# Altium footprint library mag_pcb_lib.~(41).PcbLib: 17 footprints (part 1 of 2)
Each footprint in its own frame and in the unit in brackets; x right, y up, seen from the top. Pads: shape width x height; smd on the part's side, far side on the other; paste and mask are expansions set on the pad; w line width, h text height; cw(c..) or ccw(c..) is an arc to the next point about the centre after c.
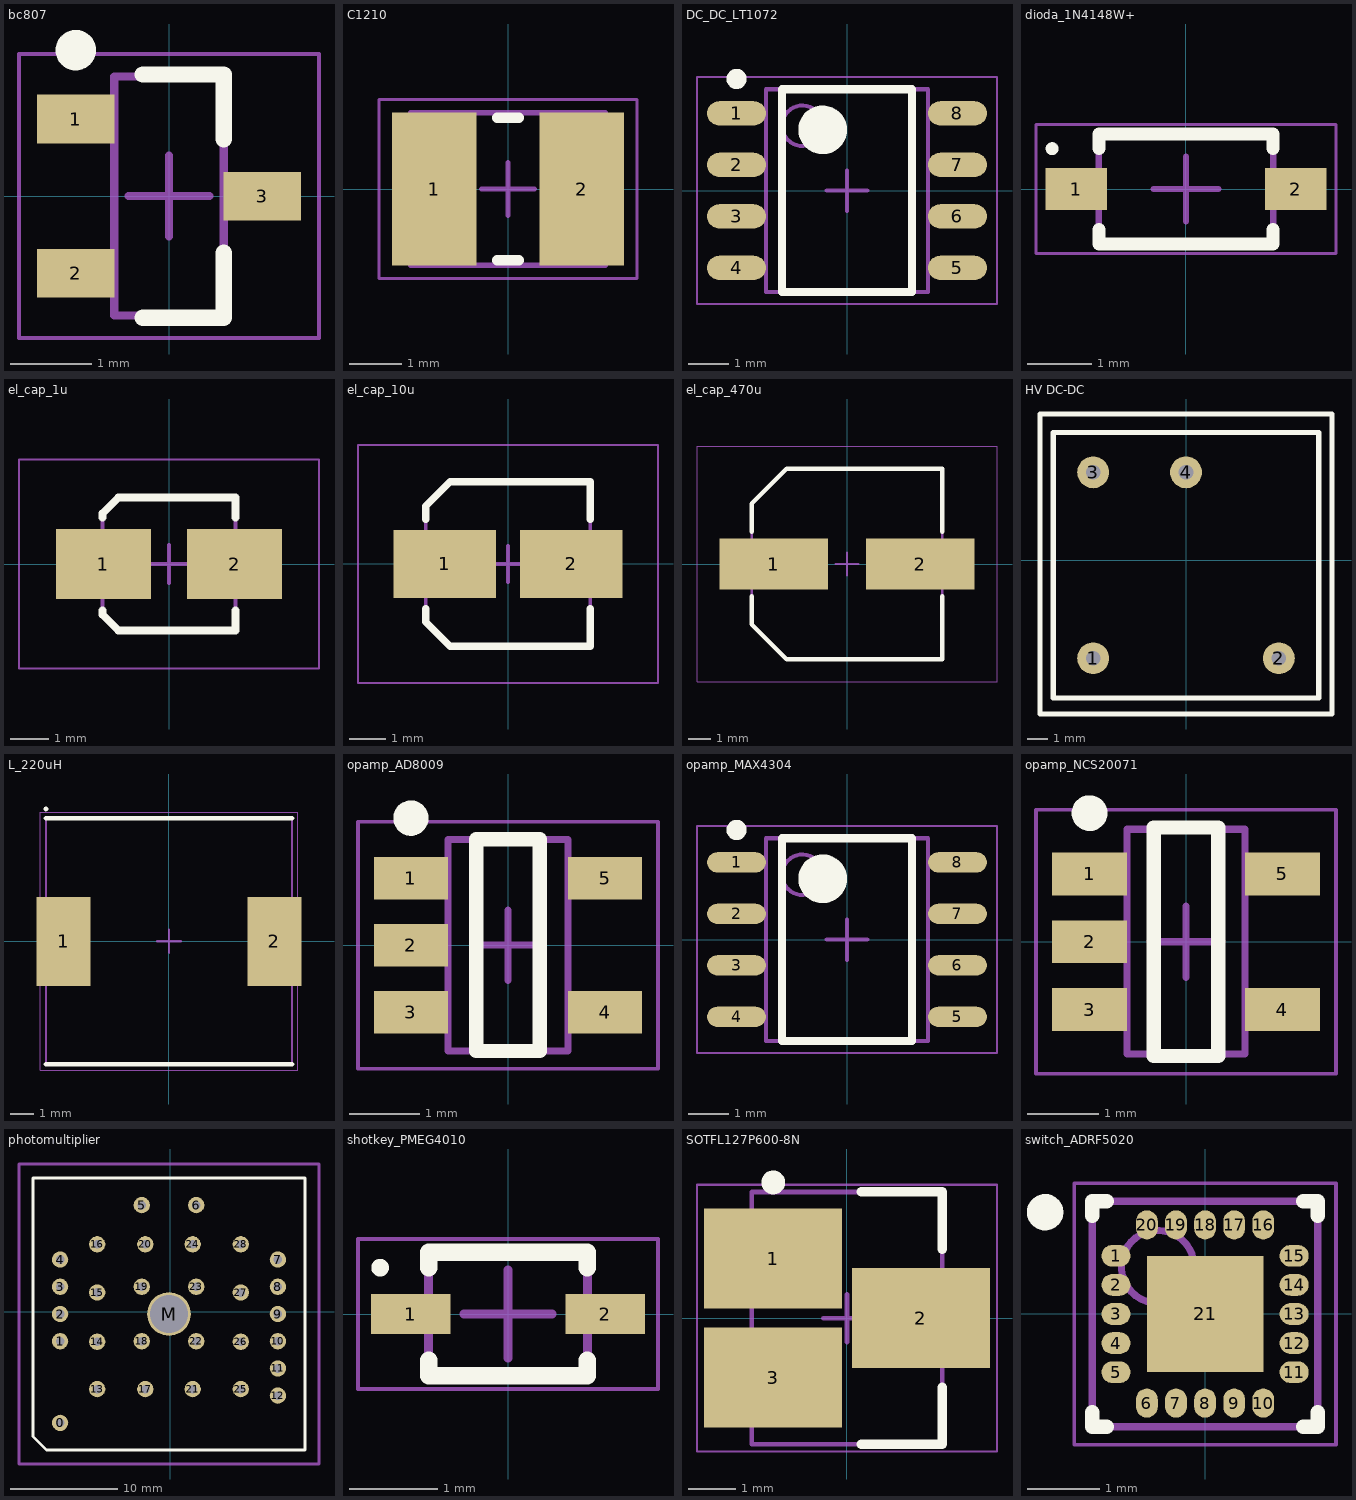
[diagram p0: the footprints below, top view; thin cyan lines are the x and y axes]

## bc807 [mm]
height 1
pads (3):
  rect 0.95x0.6 smd: 1(-1.15,0.95) 2(-1.15,-0.95) 3(1.15,0)
Top Overlay:
  circle w0.25: c-1.15,1.8 r0.125
  lines w0.2: -0.325,-1.5 0.675,-1.5 0.675,-0.7 ; -0.325,1.5 0.675,1.5 0.675,0.7
Mechanical 13:
  lines w0.1: -0.675,-1.475 0.675,-1.475 0.675,1.475 -0.675,1.475 -0.675,-1.475
Mechanical 15:
  lines w0.05: -1.85,-1.75 1.85,-1.75 1.85,1.75 -1.85,1.75 -1.85,-1.75
  lines w0.1: -0.5,0 0.5,0 ; 0,-0.5 0,0.5
3D body: height 1, standoff 0.1, extent -0.675,-1.475 0.675,1.475

## C1210 [mm]
height 1.9
pads (2):
  rect 1.6x2.9 smd: 1(-1.4,0) 2(1.4,0)
Top Overlay:
  lines w0.2: -0.2,-1.35 0.2,-1.35 ; -0.2,1.35 0.2,1.35
Mechanical 13:
  lines w0.1: -1.85,-1.45 1.85,-1.45 1.85,1.45 -1.85,1.45 -1.85,-1.45
Mechanical 15:
  lines w0.05: -2.45,-1.7 2.45,-1.7 2.45,1.7 -2.45,1.7 -2.45,-1.7
  lines w0.1: -0.5,0 0.5,0 ; 0,-0.5 0,0.5
3D body: height 1.9, standoff 0, extent 1.25,-1.45 1.85,1.45
3D body: height 1.9, standoff 0, extent -1.85,-1.45 -1.25,1.45
3D body: height 1.9, standoff 0, extent -1.25,-1.45 1.25,1.45

## DC_DC_LT1072 [mm]
height 1.76
pads (8):
  oval 1.45x0.6 smd: 1(-2.725,1.905) 2(-2.725,0.635) 3(-2.725,-0.635) 4(-2.725,-1.905) 5(2.725,-1.905) 6(2.725,-0.635) 7(2.725,0.635) 8(2.725,1.905)
Top Overlay:
  circle w0.25: c-2.725,2.755 r0.125
  circle w0.6: c-0.6,1.5 r0.3
  lines w0.2: -1.6,-2.5 -1.6,2.5 1.6,2.5 1.6,-2.5 -1.6,-2.5
Mechanical 13:
  circle w0.1: c-1.1,1.6 r0.5
  lines w0.1: -2,-2.5 -2,2.5 2,2.5 2,-2.5 -2,-2.5
Mechanical 15:
  lines w0.05: -3.7,-2.8 -3.7,2.8 3.7,2.8 3.7,-2.8 -3.7,-2.8
  lines w0.1: -0.5,0 0.5,0 ; 0,-0.5 0,0.5
3D body: height 1.76, standoff 0.25, extent -2,-2.5 2,2.5

## dioda_1N4148W+ [mm] "SODFL, 2-Leads, Body 1.60x3.80mm, IPC Medium Density"
height 1.15
pads (2):
  rect 0.95x0.65 smd: 1(-1.7,0) 2(1.7,0)
Top Overlay:
  circle w0.1: c-2.075,0.625 r0.05
  lines w0.2: -1.35,-0.625 -1.35,-0.85 1.35,-0.85 1.35,-0.625 ; -1.35,0.625 -1.35,0.85 1.35,0.85 1.35,0.625
Mechanical 13:
  lines w0.1: -1.35,-0.825 -1.35,0.825 1.35,0.825 1.35,-0.825 -1.35,-0.825
Mechanical 15:
  lines w0.05: -2.325,-1 -2.325,1 2.325,1 2.325,-1 -2.325,-1
  lines w0.1: -0.5,0 0.5,0 ; 0,-0.5 0,0.5
3D body: height 1.15, standoff 0, extent -1.35,-0.825 1.35,0.825

## el_cap_1u [mm] "Aluminum Electrolytic Capacitor, Body 3.30x3.30x5.70mm, IPC Low Density"
height 5.7
pads (2):
  rect 2.5x1.85 smd: 1(-1.725,0) 2(1.725,0)
Top Overlay:
  lines w0.2: -1.75,-1.225 -1.75,-1.338 -1.338,-1.75 1.75,-1.75 1.75,-1.225 ; -1.75,1.225 -1.75,1.338 -1.338,1.75 1.75,1.75 1.75,1.225
Mechanical 13:
  lines w0.1: -1.75,-1.338 -1.338,-1.75 1.75,-1.75 1.75,1.75 -1.338,1.75 -1.75,1.338 -1.75,-1.338
Mechanical 15:
  lines w0.05: -3.95,-2.75 -3.95,2.75 3.95,2.75 3.95,-2.75 -3.95,-2.75
  lines w0.1: -0.5,0 0.5,0 ; 0,-0.5 0,0.5
3D body: height 1.9, standoff 0, extent -1.75,-1.75 1.75,1.75
3D body: height 5.7, standoff 0, extent -1.75,-1.75 1.75,1.75

## el_cap_10u [mm] "Aluminum Electrolytic Capacitor, Body 4.30x4.30x5.70mm, IPC Low Density"
height 5.7
pads (2):
  rect 2.8x1.85 smd: 1(-1.725,0) 2(1.725,0)
Top Overlay:
  lines w0.2: -2.25,-1.225 -2.25,-1.587 -1.587,-2.25 2.25,-2.25 2.25,-1.225 ; -2.25,1.225 -2.25,1.587 -1.587,2.25 2.25,2.25 2.25,1.225
Mechanical 13:
  lines w0.1: -2.25,-1.587 -2.25,1.587 -1.587,2.25 2.25,2.25 2.25,-2.25 -1.587,-2.25 -2.25,-1.587
Mechanical 15:
  lines w0.05: -4.1,-3.25 4.1,-3.25 4.1,3.25 -4.1,3.25 -4.1,-3.25
  lines w0.1: -0.5,0 0.5,0 ; 0,-0.5 0,0.5
3D body: height 5.7, standoff 0, extent -2.25,-2.25 2.25,2.243
3D body: height 1.9, standoff 0, extent -2.25,-2.25 2.25,2.25

## el_cap_470u [mm]
height 10.5
pads (2):
  rect 4.85x2.3 smd: 1(-3.275,0) 2(3.275,0)
Top Overlay:
  lines w0.2: -4.25,-1.45 -4.25,-2.7 -2.7,-4.25 4.25,-4.25 4.25,-1.45 ; -4.25,1.45 -4.25,2.7 -2.7,4.25 4.25,4.25 4.25,1.45
Mechanical 13:
  lines w0.1: -4.25,-2.7 -4.25,2.7 -2.7,4.25 4.25,4.25 4.25,-4.25 -2.7,-4.25 -4.25,-2.7
Mechanical 15:
  lines w0.05: -6.7,-5.25 6.7,-5.25 6.7,5.25 -6.7,5.25 -6.7,-5.25
  lines w0.1: -0.5,0 0.5,0 ; 0,-0.5 0,0.5
3D body: height 10.5, standoff 0, extent -4.25,-4.25 4.25,4.25
3D body: height 3.5, standoff 0, extent -4.25,-4.25 4.25,4.25

## HV DC-DC [mil]
pads (4):
  round 60 hole 27.56: 1(-175,-185) 2(175,-185) 3(-175,165) 4(0,165)
Top Overlay:
  lines w10: -275,-290 275,-290 275,275 -275,275 -275,-290 ; -250,-260 250,-260 250,240 -250,240 -250,-260

## L_220uH [mm] "DFN, 2-Leads, Body 10.00x10.00mm, Pitch 9.00mm, IPC Medium Density"
height 5
pads (2):
  rect 2.3x3.8 smd: 1(-4.5,0) 2(4.5,0)
Top Overlay:
  circle w0.1: c-5.25,5.65 r0.05
  lines w0.2: -5.25,-5.25 5.25,-5.25 ; -5.25,5.25 5.25,5.25
Mechanical 13:
  lines w0.1: -5.25,-5.25 5.25,-5.25 5.25,5.25 -5.25,5.25 -5.25,-5.25
Mechanical 15:
  lines w0.05: -5.5,-5.5 5.5,-5.5 5.5,5.5 -5.5,5.5 -5.5,-5.5
  lines w0.1: -0.5,0 0.5,0 ; 0,-0.5 0,0.5
3D body: height 5, standoff 0, extent -5.25,-5.25 5.25,5.25

## opamp_AD8009 [mm]
height 1.45
pads (5):
  rect 1.05x0.6 smd: 1(-1.375,0.95) 2(-1.375,0) 3(-1.375,-0.95) 4(1.375,-0.95) 5(1.375,0.95)
Top Overlay:
  circle w0.25: c-1.375,1.8 r0.125
  lines w0.2: -0.45,-1.5 0.45,-1.5 0.45,1.5 -0.45,1.5 -0.45,-1.5
Mechanical 13:
  lines w0.1: -0.85,-1.5 -0.85,1.5 0.85,1.5 0.85,-1.5 -0.85,-1.5
Mechanical 15:
  lines w0.05: -2.125,-1.75 -2.125,1.75 2.125,1.75 2.125,-1.75 -2.125,-1.75
  lines w0.1: -0.5,0 0.5,0 ; 0,-0.5 0,0.5
3D body: height 1.45, standoff 0.15, extent -0.85,-1.5 0.85,1.5

## opamp_MAX4304 [mm] "SOIC, 8-Leads, Body 4.90x3.90mm, Pitch 1.27mm, IPC Medium Density"
height 1.76
pads (8):
  oval 1.45x0.5 smd: 1(-2.725,1.905) 2(-2.725,0.635) 3(-2.725,-0.635) 4(-2.725,-1.905) 5(2.725,-1.905) 6(2.725,-0.635) 7(2.725,0.635) 8(2.725,1.905)
Top Overlay:
  circle w0.25: c-2.725,2.705 r0.125
  circle w0.6: c-0.6,1.5 r0.3
  lines w0.2: -1.6,-2.5 -1.6,2.5 1.6,2.5 1.6,-2.5 -1.6,-2.5
Mechanical 13:
  circle w0.1: c-1.1,1.6 r0.5
  lines w0.1: -2,-2.5 -2,2.5 2,2.5 2,-2.5 -2,-2.5
Mechanical 15:
  lines w0.05: -3.7,-2.8 -3.7,2.8 3.7,2.8 3.7,-2.8 -3.7,-2.8
  lines w0.1: -0.5,0 0.5,0 ; 0,-0.5 0,0.5
3D body: height 1.76, standoff 0.25, extent -2,-2.5 2,2.5

## opamp_NCS20071 [mm]
height 1.1
pads (5):
  rect 1.05x0.6 smd: 1(-1.35,0.95) 2(-1.35,0) 3(-1.35,-0.95) 4(1.35,-0.95) 5(1.35,0.95)
Top Overlay:
  circle w0.25: c-1.35,1.8 r0.125
  lines w0.2: -0.45,-1.6 -0.45,1.6 0.45,1.6 0.45,-1.6 -0.45,-1.6
Mechanical 13:
  lines w0.1: -0.825,-1.575 0.825,-1.575 0.825,1.575 -0.825,1.575 -0.825,-1.575
Mechanical 15:
  lines w0.05: -2.1,-1.85 2.1,-1.85 2.1,1.85 -2.1,1.85 -2.1,-1.85
  lines w0.1: -0.5,0 0.5,0 ; 0,-0.5 0,0.5
3D body: height 1.1, standoff 0.05, extent -0.825,-1.575 0.825,1.575

## photomultiplier [mil]
pads (30):
  round 60 hole 32: 0(-403.69,-407.85) 1(-403.69,-107.85) 2(-403.69,-7.85) 3(-403.69,92.15) 4(-403.69,192.15) 5(-103.69,392.15) 6(96.31,392.15) 7(396.31,192.15) 8(396.31,92.15) 9(396.31,-7.85) 10(396.31,-107.85) 11(396.31,-207.85) 12(396.31,-307.85) 13(-267.69,-283.85) 14(-267.69,-109.85) 15(-267.69,71.15) 16(-267.69,248.15) 17(-90.69,-283.85) 18(-103.69,-107.85) 19(-103.69,92.15) 20(-90.69,248.15) 21(83.31,-283.85) 22(96.31,-107.85) 23(96.31,92.15) 24(83.31,248.15) 25(260.31,-283.85) 26(260.31,-109.85) 27(260.31,71.15) 28(260.31,248.15)
  round 160 hole 140: M(-3.69,-7.85)
Top Overlay:
  lines w10: -503.69,-457.85 -503.69,492.15 496.31,492.15 496.31,-507.85 -453.69,-507.85 -503.69,-457.85
Mechanical 4:
  lines w10: -554.87,-559.03 547.5,-559.03 547.5,543.33 -554.87,543.33 -554.87,-559.03

## shotkey_PMEG4010 [mm]
height 0.8
pads (2):
  rect 0.9x0.45 smd: 1(-1.1,0) 2(1.1,0)
Top Overlay:
  circle w0.1: c-1.45,0.525 r0.05
  lines w0.2: -0.9,-0.525 -0.9,-0.7 0.9,-0.7 0.9,-0.525 ; -0.9,0.525 -0.9,0.7 0.9,0.7 0.9,0.525
Mechanical 13:
  lines w0.1: -0.9,-0.675 0.9,-0.675 0.9,0.675 -0.9,0.675 -0.9,-0.675
Mechanical 15:
  lines w0.05: -1.7,-0.85 1.7,-0.85 1.7,0.85 -1.7,0.85 -1.7,-0.85
  lines w0.1: -0.5,0 0.5,0 ; 0,-0.5 0,0.5
3D body: height 0.8, standoff 0, extent -0.9,-0.675 0.9,0.675

## SOTFL127P600-8N [mm]
height 5.5
pads (3):
  rect 2.9x2.1 smd: 1(-1.55,1.25) 2(1.55,0) 3(-1.55,-1.25)
Top Overlay:
  circle w0.25: c-1.55,2.85 r0.125
  lines w0.2: 0.3,-2.65 2,-2.65 2,-1.45 ; 0.3,2.65 2,2.65 2,1.45
Mechanical 13:
  lines w0.1: -2,-2.65 -2,2.65 2,2.65 2,-2.65 -2,-2.65
Mechanical 15:
  lines w0.05: -3.15,-2.8 -3.15,2.8 3.15,2.8 3.15,-2.8 -3.15,-2.8
  lines w0.1: -0.5,0 0.5,0 ; 0,-0.5 0,0.5
3D body: height 5.5, standoff 0, extent -2,-2.65 2,2.65

## switch_ADRF5020 [mm] "PQFN, 20-Leads, Body 3.00x3.00mm, Pitch 0.40mm, Thermal Pad 1.60x1.60mm, IPC Medium Density"
height 0.78
pads (21):
  oval 0.4x0.3 smd: 1(-1.225,0.8) 2(-1.225,0.4) 3(-1.225,0) 4(-1.225,-0.4) 5(-1.225,-0.8) 11(1.225,-0.8) 12(1.225,-0.4) 13(1.225,0) 14(1.225,0.4) 15(1.225,0.8)
  oval 0.3x0.4 smd: 6(-0.8,-1.225) 7(-0.4,-1.225) 8(0,-1.225) 9(0.4,-1.225) 10(0.8,-1.225) 16(0.8,1.225) 17(0.4,1.225) 18(0,1.225) 19(-0.4,1.225) 20(-0.8,1.225)
  rect 1.6x1.6 smd: 21(0,0)
Top Overlay:
  circle w0.25: c-2.2,1.4 r0.125
  lines w0.2: -1.55,-1.35 -1.55,-1.55 -1.35,-1.55 ; -1.55,1.35 -1.55,1.55 -1.35,1.55 ; 1.35,-1.55 1.55,-1.55 1.55,-1.35 ; 1.35,1.55 1.55,1.55 1.55,1.35
Mechanical 13:
  circle w0.1: c-0.65,0.65 r0.5
  lines w0.1: -1.55,-1.55 -1.55,1.55 1.55,1.55 1.55,-1.55 -1.55,-1.55
Mechanical 15:
  lines w0.05: -1.8,-1.8 -1.8,1.8 1.8,1.8 1.8,-1.8 -1.8,-1.8
  lines w0.1: -0.5,0 0.5,0 ; 0,-0.5 0,0.5
3D body: height 0.78, standoff 0.16, extent -1.55,-1.55 1.55,1.55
